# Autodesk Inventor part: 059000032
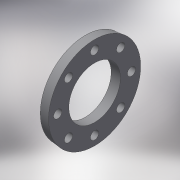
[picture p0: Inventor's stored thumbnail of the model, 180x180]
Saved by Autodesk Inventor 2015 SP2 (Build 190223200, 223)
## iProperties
Created: 2017-10
Part Number: 059000032
Material: Generic
Description: PLASSON BACKING FLANGE PVC 32
Document SubType Name: Modeling
Designer: KIM
Density: 1 g/cm^3
Appearance: Default
Author: KIM
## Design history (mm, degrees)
derived "059000.ipt"
feature "Solid1::059000.ipt"
tag "TaggingFeature1"
body "Solid1"
other parameters: "d0" = 14, "d1" = 44, "d2" = 115, "d3" = 112.7, "d5" = 14, "d6" = 42.5, "d7" = 14, "d8" = 0, "d10" = 360 deg, "D_" = 32, "E_" = 44, "E_1" = 115, "H_" = 14, "Dp_" = 85, "S_" = 14
